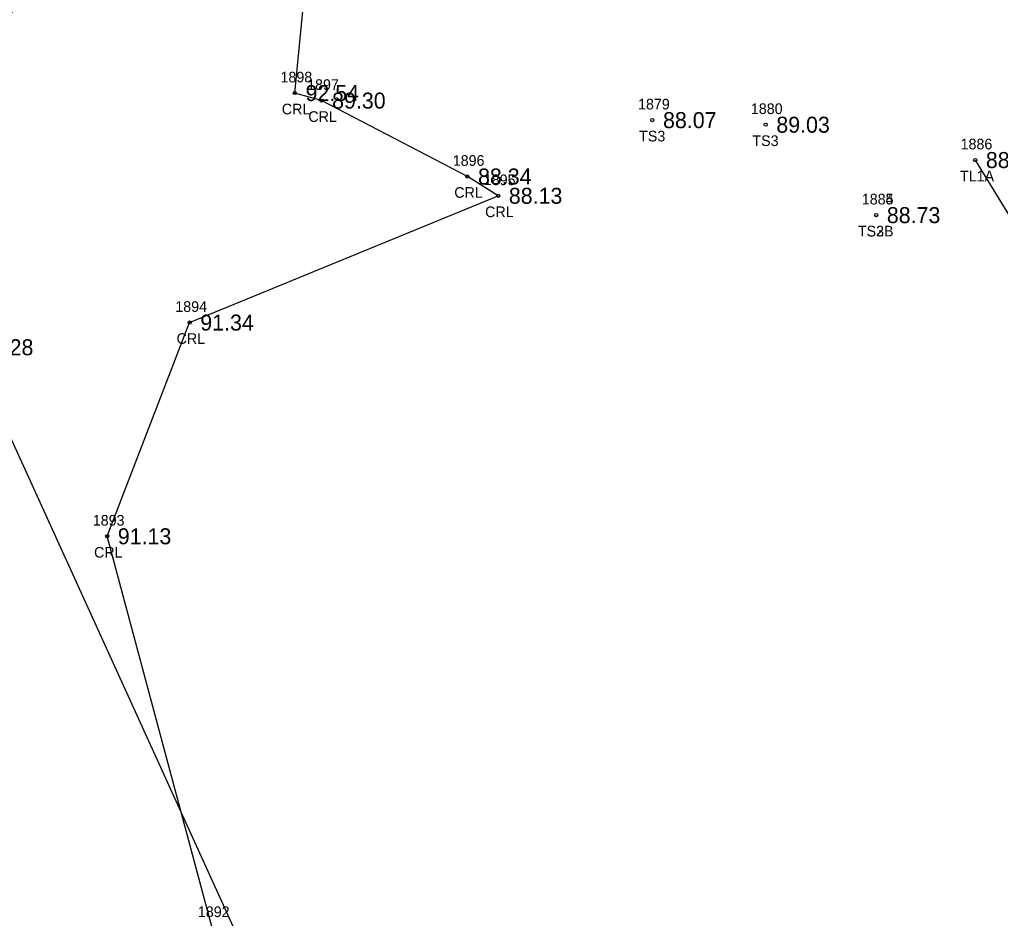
# Model space of a CAD drawing. Extents: x 2529517 to 2532038, y 935000 to 936944.
# Drawn here: x 2531034.4 to 2531126.5, y 935982.7 to 936067 of the extents above; entities that cross this region are included whole.
import ezdxf

# ---------------------------------------------------------------- set-up
doc = ezdxf.new("R2010")
doc.units = 0
for name, color, linetype in [('RD_DTM_BkLn_txCode', 7, 'Continuous'), ('RD_EX_H2O', 7, 'Continuous'), ('RD_EX_H2O_txCode', 7, 'Continuous'), ('RD_EX_TX_H2O_ELEV', 7, 'Continuous'), ('RD_EX_TX_Misc_ELEV', 7, 'Continuous'), ('RD_EX_TX_VEG_ELEV', 7, 'Continuous'), ('RD_EX_VEG', 7, 'Continuous'), ('RD_EX_VEG_txCode', 7, 'Continuous'), ('RD_SMD_Locator', 7, 'Continuous')]:
    doc.layers.add(name, color=color, linetype=linetype)

msp = doc.modelspace()

# ---------------------------------------------------------------- linework, layer by layer
at = {"layer": 'RD_EX_H2O'}
msp.add_lwpolyline([(2531078.875, 935952.281), (2531078.875, 935952.281), (2531082.899, 935955.367), (2531071.893, 935962.427), (2531052.521, 935981.817), (2531042.661, 936018.537), (2531050.401, 936038.586), (2531079.351, 936050.478), (2531076.459, 936052.289), (2531062.769, 936059.407), (2531060.273, 936060.115), (2531061.981, 936077.759), (2531053.988, 936081.477), (2531023.23, 936060.573), (2531009.04, 936063.638), (2530981.915, 936072.848), (2530952.276, 936069.689), (2530922.526, 936086.42), (2530896.36, 936118.007), (2530886.535, 936120.086), (2530870.436, 936126.503), (2530844.881, 936119.109), (2530827.398, 936131.929), (2530794.882, 936161.74)], dxfattribs=at)
at = {"layer": 'RD_EX_VEG'}
msp.add_line((2531124.108, 936053.831), (2531137.62, 936031.705), dxfattribs=at)
msp.add_lwpolyline([(2531065.966, 935956.737), (2531029.723, 936036.27), (2530913.111, 935955.889), (2530857.851, 935929.004), (2530845.595, 935970.773)], dxfattribs=at)
at = {"layer": 'RD_SMD_Locator'}
for centre in [(2531060.273, 936060.115), (2531062.769, 936059.407), (2531093.818, 936057.577), (2531104.447, 936057.146), (2531124.108, 936053.831), (2531076.459, 936052.289), (2531079.351, 936050.478), (2531114.816, 936048.665), (2531114.816, 936048.665), (2531050.401, 936038.586), (2531042.661, 936018.537)]:
    msp.add_circle(centre, 0.15, dxfattribs=at)

# ---------------------------------------------------------------- texts
at = {"layer": 'RD_DTM_BkLn_txCode'}
for s, p in [('1879', (2531092.472, 936058.577)), ('1880', (2531103.061, 936058.146)), ('TS3', (2531092.574, 936055.577)), ('TS3', (2531103.203, 936055.146)), ('1884', (2531113.469, 936049.665)), ('1885', (2531113.469, 936049.665)), ('TS2B', (2531113.099, 936046.665)), ('TS3B', (2531113.099, 936046.665))]:
    msp.add_text(s, height=1, dxfattribs=at).set_placement(p)
at = {"layer": 'RD_EX_H2O_txCode'}
for s, p in [('1898', (2531058.926, 936061.115)), ('1897', (2531061.422, 936060.407)), ('CRL', (2531059.045, 936058.115)), ('CRL', (2531061.54, 936057.407)), ('1896', (2531075.089, 936053.289)), ('1895', (2531078.004, 936051.478)), ('CRL', (2531075.231, 936050.289)), ('CRL', (2531078.122, 936048.478)), ('1894', (2531049.055, 936039.586)), ('CRL', (2531049.173, 936036.586)), ('1893', (2531041.314, 936019.537)), ('CRL', (2531041.433, 936016.537)), ('1892', (2531051.174, 935982.817))]:
    msp.add_text(s, height=1, dxfattribs=at).set_placement(p)
at = {"layer": 'RD_EX_TX_H2O_ELEV'}
for s, p in [('92.54', (2531061.273, 936059.365)), ('89.30', (2531063.769, 936058.657)), ('88.34', (2531077.459, 936051.539)), ('88.13', (2531080.351, 936049.728)), ('91.34', (2531051.401, 936037.836)), ('91.13', (2531043.661, 936017.787))]:
    msp.add_text(s, height=1.5, dxfattribs=at).set_placement(p)
at = {"layer": 'RD_EX_TX_Misc_ELEV'}
for s, p in [('88.07', (2531094.818, 936056.827)), ('89.03', (2531105.447, 936056.396)), ('88.73', (2531115.816, 936047.915)), ('88.73', (2531115.816, 936047.915))]:
    msp.add_text(s, height=1.5, dxfattribs=at).set_placement(p)
at = {"layer": 'RD_EX_TX_VEG_ELEV'}
for s, p in [('88.50', (2531125.108, 936053.081)), ('92.28', (2531030.723, 936035.52))]:
    msp.add_text(s, height=1.5, dxfattribs=at).set_placement(p)
at = {"layer": 'RD_EX_VEG_txCode'}
for s, p in [('1886', (2531122.738, 936054.831)), ('TL1A', (2531122.682, 936051.831))]:
    msp.add_text(s, height=1, dxfattribs=at).set_placement(p)

doc.saveas('drawing.dxf')
